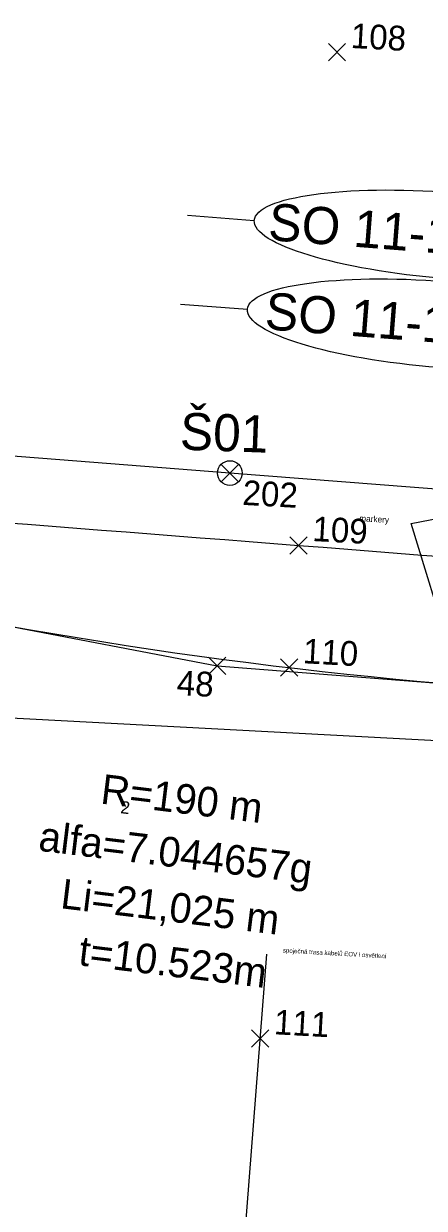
# Model space of a CAD drawing. Extents: x -669661 to -669105, y -977202 to -977030.
# Drawn here: x -669538.51 to -669522.3, y -977163.12 to -977115.22 of the extents above; entities that cross this region are included whole.
import ezdxf

# ---------------------------------------------------------------- set-up
doc = ezdxf.new("R2010")
doc.units = 0
for name, color, linetype in [('elektro-EOV', 7, 'Continuous'), ('elektro-osvetleni', 7, 'Continuous'), ('Elektro-VO+EOV', 7, 'Continuous'), ('KOL_osy', 7, 'Continuous'), ('ODV_trativody_potrubí', 7, 'Continuous'), ('ODV_trativody_šachty čísla šachet a směr toku', 7, 'Continuous'), ('ODV_šachta_popis', 7, 'Continuous'), ('POP_hlavní popis', 7, 'Continuous'), ('POP_koleje_oblouky', 7, 'Continuous'), ('POP_příčné řezy s popisem', 7, 'Continuous'), ('SO 11-10-01_vytyč_body', 7, 'Continuous'), ('SO 11-11-01_vytyč_body', 7, 'Continuous'), ('VYTY_body', 7, 'Continuous')]:
    doc.layers.add(name, color=color, linetype=linetype)

# ---------------------------------------------------------------- blocks, each defined once
blk = doc.blocks.new('POINT_DISPLAY')
for p, q in [((-0.35, -0.35), (0.35, 0.35)), ((-0.35, 0.35), (0.35, -0.35))]:
    blk.add_line(p, q)

msp = doc.modelspace()

# ---------------------------------------------------------------- linework, layer by layer
at = {"layer": 'elektro-EOV'}
for p, q in [((-669522.827, -977135.436), (-669519.569, -977134.797)), ((-669520.178, -977144.14), (-669522.827, -977135.436))]:
    msp.add_line(p, q, dxfattribs=at)
at = {"layer": 'Elektro-VO+EOV'}
msp.add_lwpolyline([(-669584.138, -977136.927), (-669559.186, -977139.528), (-669539.545, -977143.259), (-669520.014, -977144.295), (-669520.162, -977146.551), (-669517.772, -977146.771)], dxfattribs=at)
at = {"layer": 'KOL_osy'}
for points in [[(-669539.35, -977135.386), (-669538.353, -977135.464), (-669537.356, -977135.542), (-669536.359, -977135.619), (-669535.362, -977135.697), (-669534.365, -977135.774), (-669533.368, -977135.852), (-669532.371, -977135.93), (-669531.374, -977136.007), (-669530.377, -977136.085), (-669529.38, -977136.162), (-669528.383, -977136.24), (-669527.386, -977136.318), (-669526.389, -977136.395), (-669525.392, -977136.473), (-669524.395, -977136.55), (-669523.398, -977136.628), (-669522.401, -977136.706), (-669521.404, -977136.783)], [(-669539.296, -977139.536), (-669538.312, -977139.712), (-669537.327, -977139.882), (-669536.34, -977140.047), (-669535.353, -977140.207), (-669534.365, -977140.362), (-669533.377, -977140.512), (-669532.387, -977140.656), (-669531.397, -977140.795), (-669530.406, -977140.929), (-669529.414, -977141.058), (-669528.422, -977141.182), (-669527.429, -977141.3), (-669526.435, -977141.413), (-669525.441, -977141.521), (-669524.446, -977141.624), (-669523.451, -977141.721), (-669522.455, -977141.813), (-669521.459, -977141.9)]]:
    msp.add_lwpolyline(points, dxfattribs=at)
at = {"layer": 'ODV_trativody_potrubí'}
msp.add_lwpolyline([(-669495.771, -977136.07), (-669530.167, -977133.393), (-669554.095, -977131.53), (-669570.744, -977128.591)], dxfattribs=at)
at = {"layer": 'ODV_trativody_šachty čísla šachet a směr toku'}
msp.add_circle((-669530.167, -977133.393), 0.5, dxfattribs=at)
at = {"layer": 'POP_hlavní popis'}
for p, q in [((-669531.883, -977122.968), (-669529.178, -977123.178)), ((-669532.162, -977126.561), (-669529.458, -977126.772))]:
    msp.add_line(p, q, dxfattribs=at)
for centre in [(-669521.296, -977123.792), (-669521.575, -977127.386)]:
    msp.add_ellipse(centre, major_axis=(7.883, -0.614), ratio=0.220603, dxfattribs=at)
at = {"layer": 'POP_příčné řezy s popisem'}
msp.add_lwpolyline([(-669530.789, -977180.031), (-669528.672, -977152.841)], dxfattribs=at)
at = {"layer": 'VYTY_body'}
for p, q in [((-669541.016, -977139.217), (-669530.678, -977141.187)), ((-669530.678, -977141.187), (-669520.187, -977142.003))]:
    msp.add_line(p, q, dxfattribs=at)

# ---------------------------------------------------------------- block references
at = {"layer": 'SO 11-10-01_vytyč_body'}
for p in [(-669525.834, -977116.378), (-669527.386, -977136.318), (-669530.678, -977141.187), (-669527.771, -977141.259), (-669528.938, -977156.257)]:
    msp.add_blockref('POINT_DISPLAY', p, dxfattribs=at)
at = {"layer": 'SO 11-11-01_vytyč_body'}
msp.add_blockref('POINT_DISPLAY', (-669530.167, -977133.393), dxfattribs=at)

# ---------------------------------------------------------------- texts
at = {"layer": 'elektro-osvetleni'}
for s, height, p in [('markery', 0.25, (-669524.94, -977135.342)), ('spoječná trasa kabelů EOV i osvětlení', 0.18, (-669528.028, -977152.776))]:
    msp.add_text(s, height=height, rotation=356.761, dxfattribs=at).set_placement(p)
at = {"layer": 'ODV_šachta_popis'}
msp.add_text('Š01', height=1.5, rotation=357.9449, dxfattribs=at).set_placement((-669532.204, -977132.443))
at = {"layer": 'POP_hlavní popis'}
for s, p in [('SO 11-10-01', (-669528.646, -977123.969)), ('SO 11-11-01', (-669528.784, -977127.574))]:
    msp.add_text(s, height=1.5, rotation=355.549, dxfattribs=at).set_placement(p)
at = {"layer": 'POP_koleje_oblouky'}
for s, height, p in [('R=190 m', 1.2, (-669535.432, -977146.749)), ('2', 0.5, (-669534.61, -977147.14)), ('alfa=7.044657g', 1.2, (-669537.944, -977148.655)), ('Li=21,025 m', 1.2, (-669537.053, -977150.981)), ('t=10.523m', 1.2, (-669536.323, -977153.286))]:
    msp.add_text(s, height=height, rotation=353.033, dxfattribs=at).set_placement(p)
at = {"layer": 'SO 11-10-01_vytyč_body'}
for s, p in [('108', (-669525.296, -977116.204)), ('109', (-669526.848, -977136.138)), ('110', (-669527.233, -977141.08)), ('48', (-669532.334, -977142.362)), ('111', (-669528.4, -977156.08))]:
    msp.add_text(s, height=1, rotation=356.8465, dxfattribs=at).set_placement(p)
at = {"layer": 'SO 11-11-01_vytyč_body'}
msp.add_text('202', height=1, rotation=356.8465, dxfattribs=at).set_placement((-669529.676, -977134.677))

doc.saveas('drawing.dxf')
